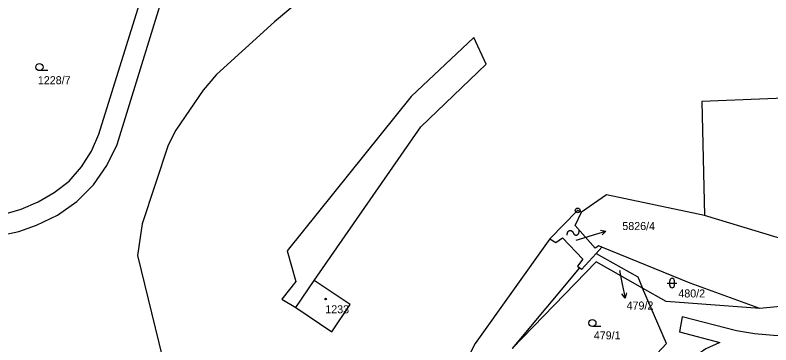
# Model space of a CAD drawing. Extents: x -737240 to -735272, y -1119606 to -1117878.
# Drawn here: x -736364.4 to -736203.8, y -1119314 to -1119244 of the extents above; entities that cross this region are included whole.
import ezdxf

# ---------------------------------------------------------------- set-up
doc = ezdxf.new("R2010")
doc.units = 0
for name, color, linetype in [('Level 1', 7, 'Continuous'), ('Level 16', 7, 'Continuous'), ('Level 18', 7, 'Continuous'), ('Level 19', 7, 'Continuous'), ('Level 25', 7, 'Continuous'), ('Level 4', 7, 'Continuous')]:
    doc.layers.add(name, color=color, linetype=linetype)

msp = doc.modelspace()

# ---------------------------------------------------------------- linework, layer by layer
at = {"layer": 'Level 1'}
for p, q in [((-736239.72, -1119293.27), (-736240.97, -1119294.63)), ((-736244.51, -1119297.69), (-736258.78, -1119314.78))]:
    msp.add_line(p, q, dxfattribs=at)
for points in [[(-736406.02, -1119188.26), (-736413.99, -1119262), (-736414, -1119265), (-736413.66, -1119268.91), (-736413.29, -1119270.8), (-736411.87, -1119274.54), (-736409.93, -1119278.12), (-736404.25, -1119283.76), (-736400.66, -1119285.68), (-736396.86, -1119286.78), (-736392.86, -1119287.18), (-736368.91, -1119286.32), (-736366.01, -1119286.05), (-736363.13, -1119285.22), (-736359.5, -1119283.68), (-736356.12, -1119281.69), (-736352.94, -1119279.25), (-736350.32, -1119276.22), (-736348.2, -1119272.9), (-736346.64, -1119269.31), (-736338, -1119241.65), (-736336.72, -1119236.91), (-736336.1, -1119233.59)], [(-736255.81, -1119210.22), (-736259.28, -1119212.27), (-736265.67, -1119215.95), (-736281.3, -1119224.06), (-736290.58, -1119229.79), (-736309.29, -1119245.48), (-736321.63, -1119256.65), (-736324.44, -1119259.95), (-736330.29, -1119268.45), (-736331.86, -1119271.65), (-736337.39, -1119288.32), (-736338.43, -1119295.05), (-736330.86, -1119325.76)], [(-736366.57, -1119290.55), (-736363.63, -1119289.96), (-736359.83, -1119288.6), (-736355.36, -1119286.51), (-736351.29, -1119283.55), (-736347.72, -1119280.02), (-736344.91, -1119275.94), (-736342.71, -1119271.47), (-736330.73, -1119232.67)], [(-736300.89, -1119300.34), (-736278.21, -1119267.73), (-736264.35, -1119254.48), (-736266.98, -1119248.79), (-736280.27, -1119261.31), (-736306.57, -1119294.06), (-736304.75, -1119300.59), (-736307.72, -1119304.29), (-736304.74, -1119306.08)], [(-736160.69, -1119260.04), (-736218.52, -1119262.39), (-736217.96, -1119286.52)], [(-736217.96, -1119286.52), (-736238.75, -1119282.17), (-736244.05, -1119285.86)], [(-736244.05, -1119285.86), (-736244.89, -1119285.47), (-736250.81, -1119291.5)], [(-736239.72, -1119293.27), (-736240.38, -1119293), (-736241.15, -1119293.46), (-736245.39, -1119288.69), (-736244.05, -1119285.86)], [(-736159.05, -1119293.03), (-736189.6, -1119293.23), (-736202.48, -1119291.23), (-736217.96, -1119286.52)], [(-736250.81, -1119291.5), (-736249.54, -1119292.31), (-736248.11, -1119291.31), (-736243.82, -1119295.84), (-736244.94, -1119297.32), (-736244.51, -1119297.69)], [(-736250.81, -1119291.5), (-736266.63, -1119313.72), (-736274.68, -1119329.65), (-736278.27, -1119338.57), (-736282.04, -1119359.23), (-736280.89, -1119363.2)], [(-736206.16, -1119306.31), (-736220.98, -1119300.9), (-736239.72, -1119293.27)], [(-736240.97, -1119294.63), (-736244.1, -1119298.04), (-736244.51, -1119297.69)], [(-736240.97, -1119294.63), (-736232.14, -1119299.54), (-736231.11, -1119301.95)], [(-736231.11, -1119301.95), (-736240.94, -1119296.36), (-736258.78, -1119314.78)], [(-736304.74, -1119306.08), (-736297.09, -1119311.21), (-736293.25, -1119305.42), (-736300.89, -1119300.34)], [(-736238.17, -1119326.72), (-736226.05, -1119313.73), (-736231.11, -1119301.95)], [(-736206.16, -1119306.31), (-736226.09, -1119304.8), (-736231.11, -1119301.95)], [(-736164.47, -1119302.93), (-736189.58, -1119304.69), (-736206.16, -1119306.31)], [(-736200.32, -1119312.15), (-736203.29, -1119312.02), (-736207.3, -1119311.69), (-736211.16, -1119311), (-736222.67, -1119308.03), (-736223.24, -1119311.21), (-736214.65, -1119313.51), (-736217.67, -1119314.87), (-736220.95, -1119317.08), (-736223.64, -1119320.01), (-736225.24, -1119322.51), (-736226.1, -1119324.39), (-736226.51, -1119326.34)]]:
    msp.add_lwpolyline(points, dxfattribs=at)
at = {"layer": 'Level 16'}
for points in [[(-736240.003, -1119289.678), (-736238.9, -1119289.865), (-736239.711, -1119290.635)], [(-736245.2, -1119291.78), (-736241.77, -1119290.74), (-736238.9, -1119289.865)], [(-736235.99, -1119298.24), (-736235.41, -1119301.12), (-736234.816, -1119304.061)], [(-736234.524, -1119302.981), (-736234.816, -1119304.061), (-736235.504, -1119303.179)]]:
    msp.add_lwpolyline(points, dxfattribs=at)
at = {"layer": 'Level 25'}
for p, q in [((-736357.448, -1119255.82), (-736359.23, -1119255.82)), ((-736225.84, -1119300.88), (-736223.84, -1119300.88)), ((-736225.34, -1119301.38), (-736225.34, -1119300.38)), ((-736224.34, -1119301.38), (-736224.34, -1119300.38)), ((-736239.978, -1119310.12), (-736241.76, -1119310.12))]:
    msp.add_line(p, q, dxfattribs=at)
msp.add_lwpolyline([(-736247.089, -1119290.719), (-736247.092, -1119290.622), (-736247.091, -1119290.531), (-736247.086, -1119290.445), (-736247.077, -1119290.365), (-736247.065, -1119290.29), (-736247.048, -1119290.22), (-736247.028, -1119290.155), (-736247.004, -1119290.096), (-736246.976, -1119290.04), (-736246.945, -1119289.99), (-736246.91, -1119289.944), (-736246.872, -1119289.902), (-736246.832, -1119289.864), (-736246.789, -1119289.831), (-736246.744, -1119289.802), (-736246.697, -1119289.778), (-736246.65, -1119289.758), (-736246.602, -1119289.743), (-736246.553, -1119289.732), (-736246.505, -1119289.725), (-736246.458, -1119289.723), (-736246.412, -1119289.726), (-736246.367, -1119289.732), (-736246.323, -1119289.742), (-736246.281, -1119289.756), (-736246.24, -1119289.772), (-736246.201, -1119289.792), (-736246.164, -1119289.814), (-736246.128, -1119289.838), (-736246.095, -1119289.864), (-736246.064, -1119289.892), (-736246.035, -1119289.921), (-736246.008, -1119289.951), (-736245.983, -1119289.982), (-736245.959, -1119290.014), (-736245.937, -1119290.048), (-736245.916, -1119290.081), (-736245.896, -1119290.116), (-736245.877, -1119290.151), (-736245.858, -1119290.187), (-736245.839, -1119290.222), (-736245.82, -1119290.258), (-736245.801, -1119290.294), (-736245.782, -1119290.33), (-736245.762, -1119290.365), (-736245.74, -1119290.4), (-736245.718, -1119290.434), (-736245.694, -1119290.467), (-736245.668, -1119290.499), (-736245.639, -1119290.529), (-736245.609, -1119290.558), (-736245.576, -1119290.585), (-736245.54, -1119290.61), (-736245.503, -1119290.633), (-736245.463, -1119290.653), (-736245.421, -1119290.671), (-736245.378, -1119290.686), (-736245.334, -1119290.698), (-736245.288, -1119290.706), (-736245.242, -1119290.711), (-736245.195, -1119290.712), (-736245.148, -1119290.708), (-736245.101, -1119290.701), (-736245.054, -1119290.69), (-736245.008, -1119290.674), (-736244.963, -1119290.654), (-736244.919, -1119290.629), (-736244.876, -1119290.6), (-736244.835, -1119290.566), (-736244.797, -1119290.528), (-736244.761, -1119290.485), (-736244.728, -1119290.437), (-736244.698, -1119290.384), (-736244.672, -1119290.326), (-736244.648, -1119290.264), (-736244.629, -1119290.198), (-736244.612, -1119290.128), (-736244.6, -1119290.053), (-736244.591, -1119289.975), (-736244.586, -1119289.893), (-736244.586, -1119289.808), (-736244.589, -1119289.719)], dxfattribs=at)
for centre, start, end in [((-736224.84, -1119300.38), 0, 180), ((-736224.84, -1119301.38), 180, 0)]:
    msp.add_arc(centre, 0.5, start, end, dxfattribs=at)
for centre, major_axis, ratio in [((-736359.23, -1119255.064), (0.764, 0), 0.9894236), ((-736244.89, -1119285.47), (0.516, 0), 0.9848078), ((-736244.89, -1119285.47), (0.0375, 0), 0.9848078), ((-736298.43, -1119304.28), (0.18, 0), 0.9848078), ((-736241.76, -1119309.364), (0.764, 0), 0.9894236)]:
    msp.add_ellipse(centre, major_axis=major_axis, ratio=ratio, dxfattribs=at)
at = {"layer": 'Level 4'}
msp.add_line((-736304.74, -1119306.08), (-736300.89, -1119300.34), dxfattribs=at)

# ---------------------------------------------------------------- texts
at = {"layer": 'Level 16'}
for s, p in [('5826/4', (-736235.4, -1119289.64)), ('479/2', (-736234.49, -1119306.5))]:
    msp.add_text(s, height=1.7, dxfattribs=at).set_placement(p)
at = {"layer": 'Level 18'}
for s, height, p in [('1228/7', 1.7, (-736359.57, -1119258.7)), ('479/2', 0.1, (-736235.99, -1119298.24)), ('480/2', 1.7, (-736223.5, -1119303.94)), ('479/1', 1.7, (-736241.46, -1119312.83))]:
    msp.add_text(s, height=height, dxfattribs=at).set_placement(p)
at = {"layer": 'Level 19'}
for s, height, p in [('5826/4', 0.1, (-736245.2, -1119291.78)), ('1233', 1.7, (-736298.505, -1119307.3))]:
    msp.add_text(s, height=height, dxfattribs=at).set_placement(p)

doc.saveas('drawing.dxf')
